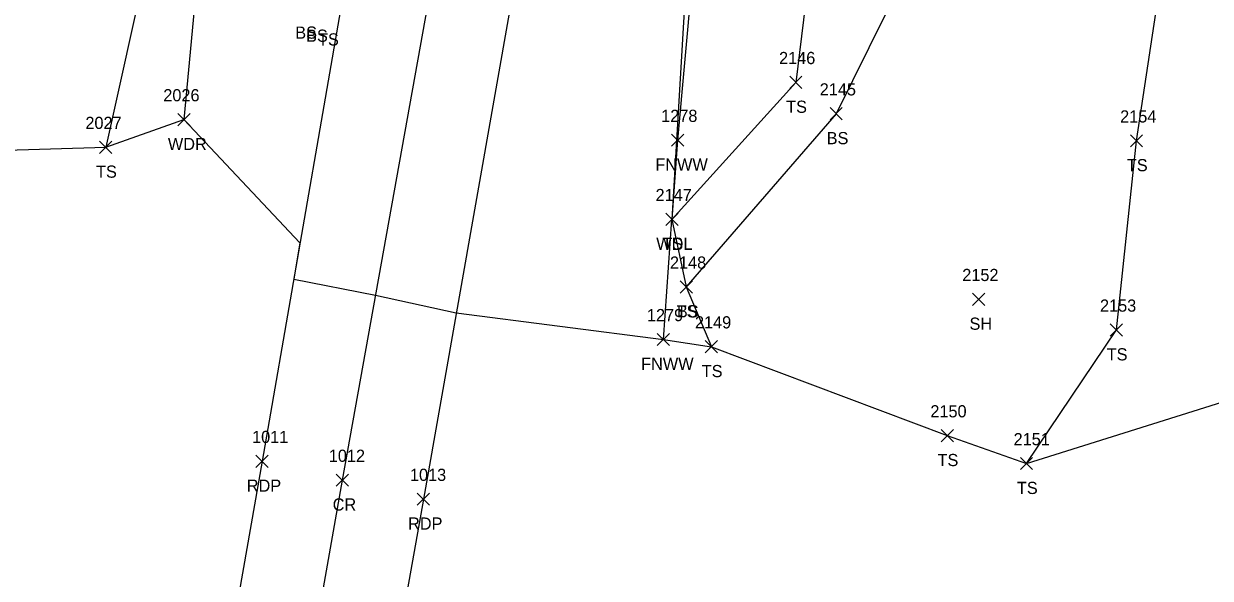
# Model space of a CAD drawing. Extents: x 1754529 to 1755810, y 621660 to 624656.
# Drawn here: x 1755421.2 to 1755616, y 623700.7 to 623791.7 of the extents above; entities that cross this region are included whole.
import ezdxf

# ---------------------------------------------------------------- set-up
doc = ezdxf.new("R2010")
doc.units = 0
for name, color, linetype in [('L_A', 7, 'Continuous'), ('L_I', 7, 'Continuous'), ('L_TIC', 7, 'Continuous'), ('LAWA', 7, 'Continuous'), ('LELB', 7, 'Continuous'), ('Level 14', 7, 'Continuous'), ('LFNC', 7, 'Continuous'), ('LSOGP', 7, 'Continuous'), ('P_A', 7, 'Continuous'), ('P_I', 7, 'Continuous'), ('PET', 7, 'Continuous'), ('PRC', 7, 'Continuous')]:
    doc.layers.add(name, color=color, linetype=linetype)

msp = doc.modelspace()

# ---------------------------------------------------------------- linework, layer by layer
at = {"layer": 'L_TIC'}
for points in [[(1755546.96, 623781.07), (1755548.96, 623783.07)], [(1755548.96, 623781.07), (1755546.96, 623783.07)], [(1755553.59, 623775.92), (1755555.59, 623777.92)], [(1755555.59, 623775.92), (1755553.59, 623777.92)], [(1755446.47, 623774.96), (1755448.47, 623776.96)], [(1755448.47, 623774.96), (1755446.47, 623776.96)], [(1755433.62, 623770.42), (1755435.62, 623772.42)], [(1755435.62, 623770.42), (1755433.62, 623772.42)], [(1755527.55, 623771.58), (1755529.55, 623773.58)], [(1755529.55, 623771.58), (1755527.55, 623773.58)], [(1755602.92, 623771.48), (1755604.92, 623773.48)], [(1755604.92, 623771.48), (1755602.92, 623773.48)], [(1755526.62, 623758.58), (1755528.62, 623760.58)], [(1755528.62, 623758.58), (1755526.62, 623760.58)], [(1755526.62, 623758.58), (1755528.62, 623760.58)], [(1755528.62, 623758.58), (1755526.62, 623760.58)], [(1755528.98, 623747.49), (1755530.98, 623749.49)], [(1755530.98, 623747.49), (1755528.98, 623749.49)], [(1755528.98, 623747.49), (1755530.98, 623749.49)], [(1755530.98, 623747.49), (1755528.98, 623749.49)], [(1755577, 623745.46), (1755579, 623747.46)], [(1755579, 623745.46), (1755577, 623747.46)], [(1755525.21, 623738.87), (1755527.21, 623740.87)], [(1755527.21, 623738.87), (1755525.21, 623740.87)], [(1755599.61, 623740.43), (1755601.61, 623742.43)], [(1755601.61, 623740.43), (1755599.61, 623742.43)], [(1755533.1, 623737.68), (1755535.1, 623739.68)], [(1755535.1, 623737.68), (1755533.1, 623739.68)], [(1755571.84, 623723.08), (1755573.84, 623725.08)], [(1755573.84, 623723.08), (1755571.84, 623725.08)], [(1755584.86, 623718.5), (1755586.86, 623720.5)], [(1755586.86, 623718.5), (1755584.86, 623720.5)]]:
    msp.add_lwpolyline(points, dxfattribs=at)
at = {"layer": 'LAWA'}
for points in [[(1755302.36, 624324.44), (1755304.56, 624259.61), (1755306.26, 624221.06), (1755317.77, 624175.11), (1755335.71, 624145.2), (1755381.51, 624131.11), (1755414.09, 624129.63), (1755447.66, 624121.7), (1755477.75, 624119.95), (1755506.85, 624141.45), (1755530.35, 624173.06), (1755521.71, 624132.68), (1755513.72, 624106.64), (1755499.73, 624051.71), (1755491.49, 624010.7), (1755483.31, 623982.28), (1755477.84, 623954.98), (1755471.72, 623930.68), (1755463.31, 623898.52), (1755457.13, 623867.77), (1755453.48, 623847.93), (1755451.28, 623827.38), (1755449.92, 623802.26), (1755447.47, 623775.96)], [(1755530.31, 623805.85), (1755527.62, 623759.58)]]:
    msp.add_lwpolyline(points, dxfattribs=at)
at = {"layer": 'LELB'}
for points in [[(1755412.5, 623921.31), (1755426.67, 623899.96), (1755438.63, 623878.37), (1755444.15, 623865.1), (1755447.69, 623848.16), (1755445.46, 623828.96), (1755441.47, 623802.31), (1755434.62, 623771.42)], [(1755598.5, 623876.91), (1755573.19, 623839.9), (1755550.78, 623804.9), (1755547.96, 623782.07), (1755527.62, 623759.58), (1755529.98, 623748.49), (1755534.1, 623738.68), (1755572.84, 623724.08), (1755585.86, 623719.5), (1755600.61, 623741.43), (1755603.92, 623772.48), (1755608.16, 623800.69), (1755612.83, 623834.4)], [(1755607.67, 623866.57), (1755585.04, 623830.52), (1755568.05, 623804.16), (1755554.59, 623776.92), (1755529.98, 623748.49)]]:
    msp.add_lwpolyline(points, dxfattribs=at)
at = {"layer": 'Level 14'}
for points in [[(1755459.3, 623718.87), (1755461.3, 623720.87)], [(1755461.3, 623718.87), (1755459.3, 623720.87)], [(1755472.47, 623715.78), (1755474.47, 623717.78)], [(1755474.47, 623715.78), (1755472.47, 623717.78)], [(1755485.8, 623712.65), (1755487.8, 623714.65)], [(1755487.8, 623712.65), (1755485.8, 623714.65)]]:
    msp.add_lwpolyline(points, dxfattribs=at)
at = {"layer": 'LFNC'}
for points in [[(1755539.8, 623880.02), (1755536, 623849.38), (1755533.19, 623824), (1755528.55, 623772.58)], [(1755528.55, 623772.58), (1755527.62, 623759.58)], [(1755526.21, 623739.87), (1755527.62, 623759.58)]]:
    msp.add_lwpolyline(points, dxfattribs=at)
at = {"layer": 'LSOGP'}
msp.add_lwpolyline([(1755354.61, 623769.01), (1755434.62, 623771.42), (1755447.47, 623775.96), (1755466.52, 623755.72), (1755465.49, 623749.74), (1755478.92, 623747.14), (1755492.19, 623744.22), (1755526.21, 623739.87), (1755534.1, 623738.68), (1755572.84, 623724.08), (1755585.86, 623719.5), (1755619.86, 623730.16)], dxfattribs=at)
at = {"layer": 'PET'}
for points in [[(1755535.07, 624132.59), (1755507.27, 623983.72), (1755476.9, 623815.46), (1755460.3, 623719.87), (1755437.79, 623591.8), (1755421.36, 623504.45), (1755418.26, 623495.73), (1755404.2, 623424.5), (1755397.43, 623386.49), (1755390.98, 623344.71), (1755391.72, 623340.77), (1755385.02, 623296.56), (1755379.33, 623252.08), (1755376.53, 623216.25), (1755375.95, 623174.43), (1755377.19, 623132.58)], [(1755561.91, 624125.77), (1755533.66, 623976.91), (1755504.04, 623811.48), (1755486.8, 623713.65), (1755464.22, 623587.1), (1755446.31, 623490.47), (1755433.28, 623420.6), (1755425.75, 623380.35), (1755417.64, 623332.29), (1755411.38, 623292.51), (1755405.94, 623251.45), (1755403.49, 623215.07), (1755403.14, 623175.05), (1755404.1, 623131.29)]]:
    msp.add_lwpolyline(points, dxfattribs=at)
at = {"layer": 'PRC'}
msp.add_lwpolyline([(1755548.82, 624129.6), (1755520.89, 623980.45), (1755490.93, 623813.93), (1755473.47, 623716.78), (1755450.77, 623588.43), (1755432.8, 623492.49), (1755420.05, 623422.21), (1755412.93, 623383.28), (1755404.64, 623333.82), (1755398.35, 623294.75), (1755393.11, 623251.83), (1755390.3, 623215.98), (1755389.28, 623175.01), (1755390.29, 623132.74)], dxfattribs=at)

# ---------------------------------------------------------------- texts
at = {"layer": 'L_A'}
for s, p in [('BS', (1755465.75, 623789.24)), ('BS', (1755467.53, 623788.73)), ('TS', (1755469.49, 623788.12)), ('TS', (1755546.37, 623777.07)), ('BS', (1755553.03, 623771.92)), ('WDR', (1755444.83, 623770.96)), ('TS', (1755433.03, 623766.42)), ('FNWW', (1755524.89, 623767.58)), ('TS', (1755602.33, 623767.48)), ('WDL', (1755525.04, 623754.58)), ('TS', (1755526.03, 623754.58)), ('TS', (1755528.39, 623743.49)), ('BS', (1755528.43, 623743.49)), ('SH', (1755576.49, 623741.46)), ('TS', (1755599.02, 623736.43)), ('FNWW', (1755522.56, 623734.87)), ('TS', (1755532.51, 623733.68)), ('TS', (1755571.24, 623719.08)), ('TS', (1755584.27, 623714.5))]:
    msp.add_text(s, height=2, dxfattribs=at).set_placement(p)
at = {"layer": 'L_I'}
for s, p in [('2146', (1755545.21, 623785.07)), ('2145', (1755551.89, 623779.92)), ('2026', (1755444.08, 623778.96)), ('2027', (1755431.28, 623774.42)), ('1278', (1755525.85, 623775.58)), ('2154', (1755601.23, 623775.48)), ('2147', (1755524.93, 623762.58)), ('2147', (1755524.93, 623762.58)), ('2148', (1755527.29, 623751.49)), ('2148', (1755527.29, 623751.49)), ('2152', (1755575.3, 623749.46)), ('1279', (1755523.51, 623742.87)), ('2153', (1755597.92, 623744.43)), ('2149', (1755531.4, 623741.68)), ('2150', (1755570.06, 623727.08)), ('2151', (1755583.73, 623722.5))]:
    msp.add_text(s, height=2, dxfattribs=at).set_placement(p)
at = {"layer": 'P_A'}
for s, p in [('RDP', (1755457.79, 623714.87)), ('CR', (1755471.9, 623711.78)), ('RDP', (1755484.28, 623708.65))]:
    msp.add_text(s, height=2, dxfattribs=at).set_placement(p)
at = {"layer": 'P_I'}
for s, p in [('1011', (1755458.66, 623722.87)), ('1012', (1755471.26, 623719.78)), ('1013', (1755484.59, 623716.65))]:
    msp.add_text(s, height=2, dxfattribs=at).set_placement(p)

doc.saveas('drawing.dxf')
